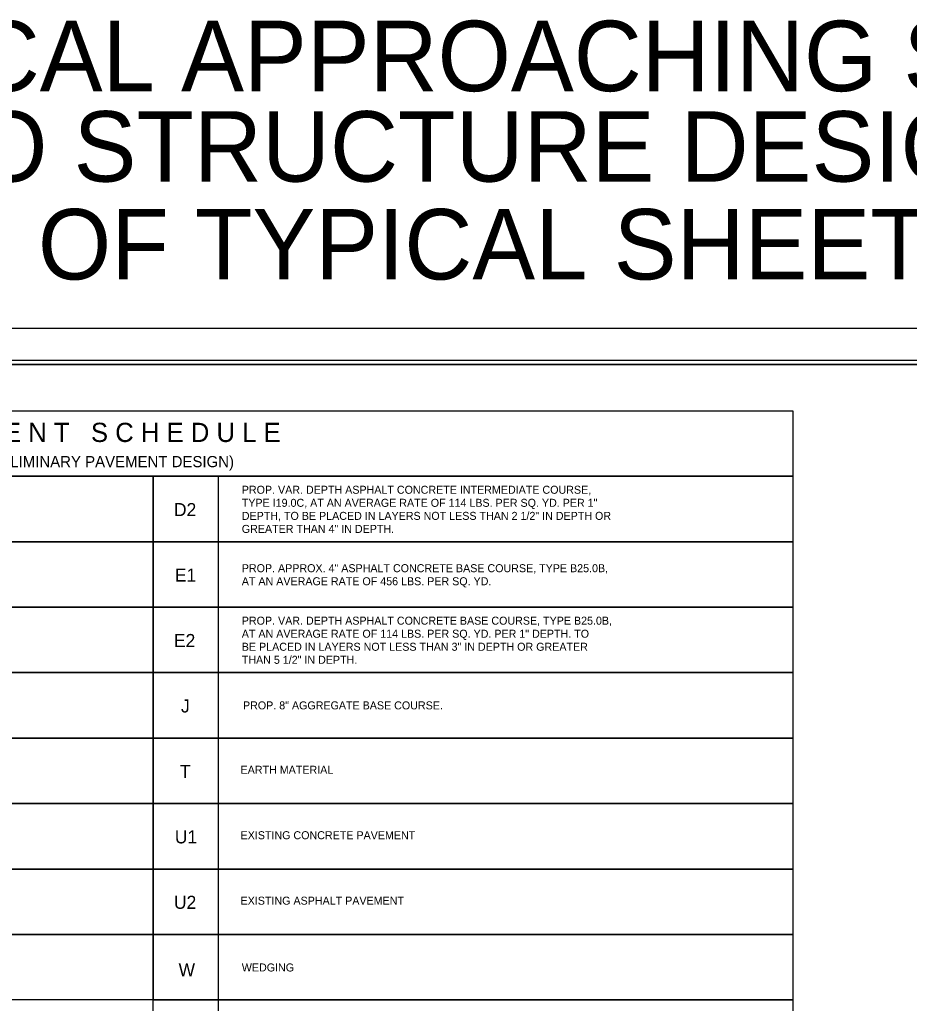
# Model space of a CAD drawing. Extents: x 2241081 to 2251104, y 658534 to 663427.
# Drawn here: x 2243322 to 2243878, y 662416 to 663031 of the extents above; entities that cross this region are included whole.
import ezdxf

# ---------------------------------------------------------------- set-up
doc = ezdxf.new("R2010")
doc.units = 0
for name, color, linetype in [('Old_Level_2', 7, 'Continuous'), ('Prop Pavement Schedule Description CELL', 7, 'Continuous'), ('Sheet Cutting Line CELL', 7, 'Continuous'), ('Sheet Plan CELL', 7, 'Continuous'), ('Sheet Plot Border Inside CELL', 7, 'Continuous'), ('Sheet Plot Border Outside CELL', 7, 'Continuous'), ('Typical Text Label CELL', 7, 'Continuous')]:
    doc.layers.add(name, color=color, linetype=linetype)

msp = doc.modelspace()

# ---------------------------------------------------------------- linework, layer by layer
at = {"layer": 'Old_Level_2'}
msp.add_lwpolyline([(2243045.86, 662540.96), (2243004.95, 662540.96), (2243004.95, 662581.87), (2243404.95, 662581.87), (2243404.95, 662540.96), (2243045.86, 662540.96), (2243045.86, 662581.87)], dxfattribs=at)
at = {"layer": 'Prop Pavement Schedule Description CELL'}
msp.add_lwpolyline([(2243004.95, 662786.42), (2243804.97, 662786.42), (2243804.97, 662745.52), (2243004.95, 662745.52)], close=True, dxfattribs=at)
for points in [[(2243045.86, 662704.61), (2243004.95, 662704.61), (2243004.95, 662745.52), (2243404.95, 662745.52), (2243404.95, 662704.61), (2243045.86, 662704.61), (2243045.86, 662745.52)], [(2243445.86, 662704.61), (2243404.95, 662704.61), (2243404.95, 662745.52), (2243804.96, 662745.52), (2243804.96, 662704.61), (2243445.86, 662704.61), (2243445.86, 662745.52)], [(2243045.86, 662663.7), (2243004.95, 662663.7), (2243004.95, 662704.61), (2243404.95, 662704.61), (2243404.95, 662663.7), (2243045.86, 662663.7), (2243045.86, 662704.61)], [(2243445.86, 662663.7), (2243404.95, 662663.7), (2243404.95, 662704.61), (2243804.95, 662704.61), (2243804.95, 662663.7), (2243445.86, 662663.7), (2243445.86, 662704.61)], [(2243045.86, 662622.78), (2243004.95, 662622.78), (2243004.95, 662663.7), (2243404.95, 662663.7), (2243404.95, 662622.78), (2243045.86, 662622.78), (2243045.86, 662663.7)], [(2243445.86, 662622.79), (2243404.95, 662622.79), (2243404.95, 662663.7), (2243804.95, 662663.7), (2243804.95, 662622.79), (2243445.86, 662622.79), (2243445.86, 662663.7)], [(2243045.86, 662581.87), (2243004.95, 662581.87), (2243004.95, 662622.78), (2243404.95, 662622.78), (2243404.95, 662581.87), (2243045.86, 662581.87), (2243045.86, 662622.78)], [(2243445.86, 662581.88), (2243404.95, 662581.88), (2243404.95, 662622.79), (2243804.96, 662622.79), (2243804.96, 662581.88), (2243445.86, 662581.88), (2243445.86, 662622.79)], [(2243445.86, 662540.97), (2243404.95, 662540.97), (2243404.95, 662581.88), (2243804.95, 662581.88), (2243804.95, 662540.97), (2243445.86, 662540.97), (2243445.86, 662581.88)], [(2243045.86, 662500.04), (2243004.95, 662500.04), (2243004.95, 662540.96), (2243404.95, 662540.96), (2243404.95, 662500.04), (2243045.86, 662500.04), (2243045.86, 662540.96)], [(2243445.86, 662500.07), (2243404.95, 662500.07), (2243404.95, 662540.97), (2243804.95, 662540.97), (2243804.95, 662500.07), (2243445.86, 662500.07), (2243445.86, 662540.97)], [(2243045.86, 662459.13), (2243004.95, 662459.13), (2243004.95, 662500.04), (2243404.95, 662500.04), (2243404.95, 662459.13), (2243045.86, 662459.13), (2243045.86, 662500.04)], [(2243445.86, 662459.16), (2243404.95, 662459.16), (2243404.95, 662500.07), (2243804.95, 662500.07), (2243804.95, 662459.16), (2243445.86, 662459.16), (2243445.86, 662500.07)], [(2243045.86, 662418.22), (2243004.95, 662418.22), (2243004.95, 662459.13), (2243404.95, 662459.13), (2243404.95, 662418.22), (2243045.86, 662418.22), (2243045.86, 662459.13)], [(2243445.86, 662418.25), (2243404.95, 662418.25), (2243404.95, 662459.16), (2243804.96, 662459.16), (2243804.96, 662418.25), (2243445.86, 662418.25), (2243445.86, 662459.16)], [(2243445.86, 662377.34), (2243404.95, 662377.34), (2243404.95, 662418.25), (2243804.96, 662418.25), (2243804.96, 662377.34), (2243445.86, 662377.34), (2243445.86, 662418.25)]]:
    msp.add_lwpolyline(points, dxfattribs=at)
at = {"layer": 'Sheet Cutting Line CELL'}
msp.add_line((2244489.63, 662837.89), (2242806.13, 662837.89), dxfattribs=at)
at = {"layer": 'Sheet Plan CELL'}
for points in [[(2242972.61, 661765.4), (2242972.59, 662815.38), (2244272.58, 662815.42), (2244272.59, 662665.35), (2244472.63, 662665.34), (2244472.63, 661765.4)], [(2244472.65, 662815.4), (2242972.62, 662815.4), (2242972.61, 661765.4), (2244472.63, 661765.4)]]:
    msp.add_lwpolyline(points, close=True, dxfattribs=at)
at = {"layer": 'Sheet Plot Border Inside CELL'}
msp.add_lwpolyline([(2242819.13, 661762.89), (2244485.11, 661762.9), (2244485.13, 662817.89), (2242819.13, 662817.89)], close=True, dxfattribs=at)
at = {"layer": 'Sheet Plot Border Outside CELL'}
msp.add_lwpolyline([(2242806.13, 661742.89), (2244489.63, 661742.89), (2244489.63, 662837.89), (2242806.13, 662837.89)], close=True, dxfattribs=at)

# ---------------------------------------------------------------- texts
at = {"layer": 'Prop Pavement Schedule Description CELL'}
for s, height, p in [('P A V E M E N T   S C H E D U L E', 12, (2243233.29, 662766.96)), ('(PRELIMINARY PAVEMENT DESIGN)', 7, (2243293.32, 662751.19)), ('PROP. VAR. DEPTH ASPHALT CONCRETE INTERMEDIATE COURSE,', 5, (2243460.44, 662734.6)), ('D2', 8.167, (2243418.02, 662720.61)), ('TYPE I19.0C, AT AN AVERAGE RATE OF 114 LBS. PER SQ. YD. PER 1" ', 5, (2243460.44, 662726.44)), ('DEPTH, TO BE PLACED IN LAYERS NOT LESS THAN 2 1/2" IN DEPTH OR', 5, (2243460.44, 662718.28)), ('GREATER THAN 4" IN DEPTH.', 5, (2243460.44, 662710.12)), ('PROP. APPROX. 4" ASPHALT CONCRETE BASE COURSE, TYPE B25.0B,', 5, (2243460.44, 662685.57)), ('E1', 8.167, (2243418.59, 662679.69)), ('AT AN AVERAGE RATE OF 456 LBS. PER SQ. YD.', 5, (2243460.44, 662677.41)), ('PROP. VAR. DEPTH ASPHALT CONCRETE BASE COURSE, TYPE B25.0B,', 5, (2243460.44, 662652.78)), ('AT AN AVERAGE RATE OF 114 LBS. PER SQ. YD. PER 1" DEPTH. TO', 5, (2243460.44, 662644.62)), ('E2', 8.167, (2243418.02, 662638.78)), ('BE PLACED IN LAYERS NOT LESS THAN 3" IN DEPTH OR GREATER', 5, (2243460.44, 662636.47)), ('THAN 5 1/2" IN DEPTH.', 5, (2243460.44, 662628.31)), ('J', 8.17, (2243422.45, 662597.88)), ('PROP. 8" AGGREGATE BASE COURSE.', 5, (2243461.19, 662599.83)), ('T', 8.17, (2243421.76, 662556.97)), ('EARTH MATERIAL', 5, (2243459.68, 662559.59)), ('U1', 8.167, (2243418.59, 662516.07)), ('EXISTING CONCRETE PAVEMENT', 5, (2243459.68, 662518.68)), ('U2', 8.167, (2243418.02, 662475.16)), ('EXISTING ASPHALT PAVEMENT', 5, (2243459.68, 662477.77)), ('W', 8.17, (2243420.92, 662433.01)), ('WEDGING', 5, (2243460.44, 662436.03))]:
    msp.add_text(s, height=height, dxfattribs=at).set_placement(p)
at = {"layer": 'Typical Text Label CELL'}
for s, p in [('TYPICAL APPROACHING STRUCTURE', (2243160.68, 662986.2)), ('AS SENT TO STRUCTURE DESIGN ON 05/07/13', (2242988.76, 662929.67)), ("(NOT PART OF TYPICAL SHEETS, DON'T DELETE)", (2242999.27, 662868.53))]:
    msp.add_text(s, height=44.0423, dxfattribs=at).set_placement(p)

doc.saveas('drawing.dxf')
